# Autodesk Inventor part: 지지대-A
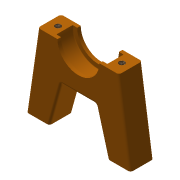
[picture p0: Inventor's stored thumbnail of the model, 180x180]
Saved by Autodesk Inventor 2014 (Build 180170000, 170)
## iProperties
Created: 2018-01
Part Number: 지지대-A
Material: Aluminum 6061
Document SubType Name: Modeling
Designer: mduedu
Density: 2.71 g/cm^3
Mass: 21.9456 g
Surface Area: 38.5771 cm^2
Volume: 8.09801 cm^3
Appearance: Orange
Author: mduedu
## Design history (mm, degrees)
sketch "스케치1"
  geometry: L1 (-22.5, 0)-(22.5, 0); L2 (22.5, 0)-(17.5, 34); L3 (17.5, 34)-(-17.5, 34); L4 (-17.5, 34)-(-22.5, 0); 3 further points
  constraints: 8 end point, 2 midpoint, 1 coincident, 1 horizontal, 1 parallel, 1 vertical alignment
  dimensions: "d0" = 45 distance of L1.start L1.end; "d3" = 35 distance of L2.end L3.end; "d4" = 34 vertical distance of L1.end L2.end
extrude "돌출1" new body sketch "스케치1" stored distance "d5" = 10; taper "d6" = 0 deg
sketch "스케치2"
  geometry: L1 (-12.5, 0)-(12.5, 0); L2 (12.5, 0)-(7.5, 18); L3 (7.5, 18)-(-7.5, 18); L4 (-7.5, 18)-(-12.5, 0); L5 (-22.5, 0)-(22.5, 0) reference; 4 further points
  constraints: 8 end point, 4 midpoint, 1 horizontal, 1 parallel, 1 vertical alignment
  dimensions: "d7" = 10 distance of L1.start L5.start; "d8" = 10 distance of L1.end L5.end (derived); "d9" = 15 distance of L2.end L3.end; "d10" = 18 distance between parallel lines of L1 L3
extrude "돌출2" cut sketch "스케치2" stored distance "d11" = 10; taper "d12" = 0 deg
sketch "스케치3"
  geometry: L1 (-17.5, 34)-(17.5, 34) reference; C1 r 11 at (0, 34); C2 r 9 at (0, 34); 1 further point
  constraints: 2 centre point, 1 coincident, 1 midpoint
  dimensions: "d13" = 22 diameter of C1; "d16" = 18 diameter of C2
extrude "돌출3" cut sketch "스케치3" stored distance "d14" = 7; taper "d15" = 0 deg
extrude "돌출4" cut sketch "스케치3" stored distance "d17" = 7; taper "d18" = 0 deg
fillet "모깎기1" dims "d19" = 0.3
fillet "모깎기2" dims "d20" = 1
fillet "모깎기3" dims "d21" = 1
fillet "모깎기4" dims "d22" = 1
sketch "스케치4"
  geometry: 2 further points
  constraints: 2 other
hole "구멍1" sketch "스케치4" at (-22.771, -3.5), (4.771, -3.5) diameter "d23" = 2.459; stored, may be unused: countersink angle "d27" = 90 deg, drill point angle "d29" = 120 deg; dims "d24" = 4.5, "d25" = 4, "d26" = 2, "d28" = 6
sketch "스케치5"
  geometry: 4 further points
  constraints: 4 other
hole "구멍2" sketch "스케치5" at (40, 4), (5, -27), (40, -27), (5, 4) diameter "d30" = 2.459; stored, may be unused: countersink angle "d34" = 90 deg, drill point angle "d36" = 120 deg; dims "d31" = 6.9, "d32" = 4, "d33" = 2, "d35" = 8.4
node "솔리드1"
